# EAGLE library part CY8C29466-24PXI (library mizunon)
Cypress PSoC 29466 Cypress PSoC 29466
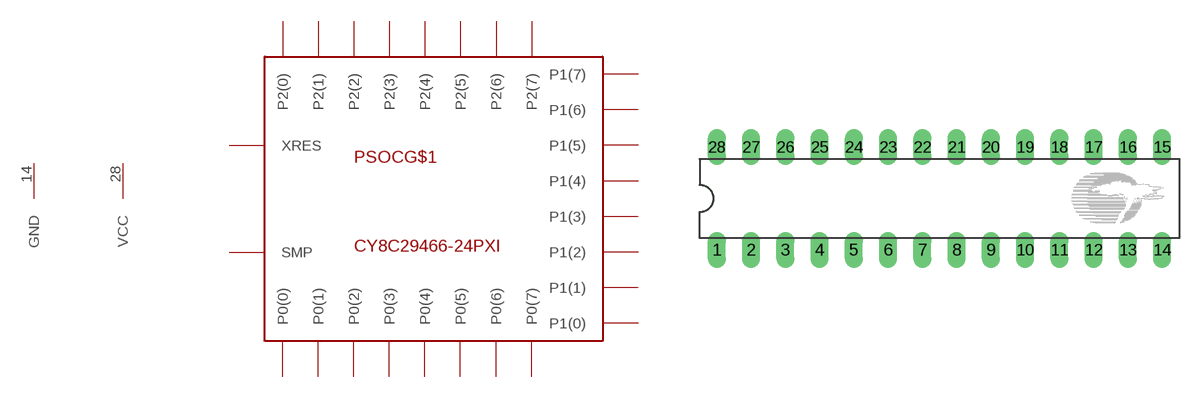
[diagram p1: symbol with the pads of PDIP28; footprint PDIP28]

Designator prefix PSOC; gates G$1=CY8C29466-24* G$2=VCC G$3=GND

## CY8C29466-24PXI  [PDIP28]
1  G$1:P0(7)
2  G$1:P0(5)
3  G$1:P0(3)
4  G$1:P0(1)
5  G$1:P2(7)
6  G$1:P2(5)
7  G$1:P2(3)
8  G$1:P2(1)
9  G$1:SMP  out
10  G$1:P1(7)
11  G$1:P1(5)
12  G$1:P1(3)
13  G$1:P1(1)
14  G$3:GND  pwr
15  G$1:P1(0)
16  G$1:P1(2)
17  G$1:P1(4)
18  G$1:P1(6)
19  G$1:XRES  in
20  G$1:P2(0)
21  G$1:P2(2)
22  G$1:P2(4)
23  G$1:P2(6)
24  G$1:P0(0)
25  G$1:P0(2)
26  G$1:P0(4)
27  G$1:P0(6)
28  G$2:VCC  pwr

## Footprint PDIP28 (pad centres in mm)
drill 0.813 long: 1 -16.51,-3.81; 2 -13.97,-3.81; 3 -11.43,-3.81; 4 -8.89,-3.81; 5 -6.35,-3.81; 6 -3.81,-3.81; 7 -1.27,-3.81; 8 1.27,-3.81; 9 3.81,-3.81; 10 6.35,-3.81; 11 8.89,-3.81; 12 11.43,-3.81; 13 13.97,-3.81; 14 16.51,-3.81; 15 16.51,3.81; 16 13.97,3.81; 17 11.43,3.81; 18 8.89,3.81; 19 6.35,3.81; 20 3.81,3.81; 21 1.27,3.81; 22 -1.27,3.81; 23 -3.81,3.81; 24 -6.35,3.81; 25 -8.89,3.81; 26 -11.43,3.81; 27 -13.97,3.81; 28 -16.51,3.81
